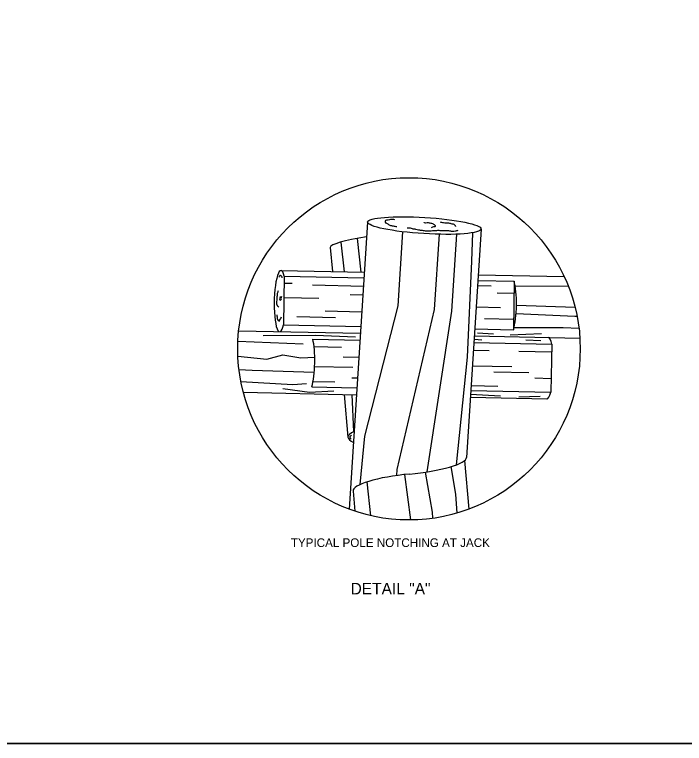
# Model space of a CAD drawing. Extents: x 49991.4 to 50021, y 49987.6 to 50011.4.
# Drawn here: x 50004.07 to 50008.69, y 49987.8 to 49992.83 of the extents above; entities that cross this region are included whole.
import ezdxf

# ---------------------------------------------------------------- set-up
doc = ezdxf.new("R2010")
doc.units = 0
for name, color, linetype in [('Level 1', 7, 'Continuous'), ('Level 2', 7, 'Continuous'), ('Level 3', 7, 'Continuous')]:
    doc.layers.add(name, color=color, linetype=linetype)

msp = doc.modelspace()

# ---------------------------------------------------------------- linework, layer by layer
at = {"layer": 'Level 1'}
for p, q in [((50006.5042, 49991.3972), (50006.376, 49989.4157)), ((50007.2869, 49991.3492), (50007.1873, 49989.7729)), ((50006.2469, 49991.2221), (50006.2626, 49991.0556)), ((50005.9062, 49991.0632), (50006.481, 49991.0506)), ((50005.9295, 49991.0237), (50005.925, 49990.6879)), ((50005.9295, 49991.0237), (50006.4785, 49991.0117)), ((50007.267, 49991.0336), (50007.8605, 49991.0205)), ((50005.9287, 49990.9761), (50005.9838, 49990.9749)), ((50006.125, 49990.9635), (50006.475, 49990.9558)), ((50007.2622, 49990.9583), (50007.3565, 49990.9563)), ((50007.2645, 49990.9946), (50007.5141, 49990.989)), ((50007.5141, 49990.989), (50007.5094, 49990.6535)), ((50007.3976, 49990.9099), (50007.5131, 49990.9073)), ((50005.9274, 49990.8762), (50006.1668, 49990.8713)), ((50006.384, 49990.8964), (50006.4711, 49990.8946)), ((50007.2529, 49990.8112), (50007.42, 49990.8074)), ((50006.2114, 49990.7843), (50006.4637, 49990.7786)), ((50006.0157, 49990.7443), (50006.282, 49990.7385)), ((50007.311, 49990.7324), (50007.5105, 49990.7281)), ((50005.925, 49990.6879), (50006.4571, 49990.6763)), ((50007.2433, 49990.6593), (50007.5095, 49990.6535)), ((50005.6148, 49990.6476), (50006.4539, 49990.6294)), ((50007.2404, 49990.6121), (50007.9685, 49990.5964)), ((50007.2612, 49990.6328), (50007.3729, 49990.6249)), ((50007.4886, 49990.6195), (50007.704, 49990.6275)), ((50006.1257, 49990.5897), (50006.453, 49990.5826)), ((50007.2374, 49990.5654), (50007.775, 49990.5537)), ((50007.2932, 49990.581), (50007.2413, 49990.5876)), ((50007.7, 49990.577), (50007.5963, 49990.5823)), ((50007.775, 49990.5537), (50007.7679, 49990.2235)), ((50006.1345, 49990.5387), (50006.3236, 49990.5345)), ((50007.2342, 49990.5142), (50007.3417, 49990.5118)), ((50007.5481, 49990.5069), (50007.7738, 49990.5018)), ((50006.3357, 49990.4673), (50006.4435, 49990.4647)), ((50006.1387, 49990.4013), (50006.4027, 49990.3956)), ((50007.2273, 49990.4057), (50007.5001, 49990.3999)), ((50007.376, 49990.3644), (50007.616, 49990.3591)), ((50006.3956, 49990.3232), (50006.4342, 49990.3224)), ((50007.6572, 49990.321), (50007.7699, 49990.3185)), ((50006.1186, 49990.2592), (50006.4279, 49990.2525)), ((50006.1275, 49990.2968), (50006.2778, 49990.2934)), ((50007.2186, 49990.2681), (50007.4017, 49990.2641)), ((50005.6468, 49990.2227), (50006.4267, 49990.2058)), ((50006.3413, 49990.2075), (50006.3688, 49989.9117)), ((50006.3961, 49990.2065), (50006.4058, 49989.9503)), ((50007.215, 49990.2103), (50007.4201, 49990.1989)), ((50007.2166, 49990.2354), (50007.7679, 49990.2235)), ((50007.2136, 49990.1884), (50007.7425, 49990.1772)), ((50007.5464, 49990.191), (50007.694, 49990.1949)), ((50007.1721, 49989.7505), (50007.2032, 49989.4158)), ((50006.4035, 49989.5407), (50006.4165, 49989.4014))]:
    msp.add_line(p, q, dxfattribs=at)
msp.add_lwpolyline([(49999.3835, 49998.9992), (50016.7501, 49998.9992), (50016.7501, 49987.7988), (49999.3835, 49987.7988)], close=True, dxfattribs=at)
for points in [[(50006.4517, 49989.5854), (50006.4858, 49989.9202), (50006.715, 49990.8191), (50006.7477, 49991.3301)], [(50006.7067, 49989.6479), (50006.7083, 49989.6902), (50006.9661, 49990.793), (50006.9996, 49991.3128)], [(50006.9153, 49989.6732), (50007.0848, 49990.7813), (50007.1195, 49991.3137)], [(50007.1178, 49989.7222), (50007.1936, 49990.4653), (50007.2222, 49991.1271), (50007.2295, 49991.3238)], [(50006.3436, 49991.0536), (50006.3212, 49991.2596)], [(50006.4596, 49991.0511), (50006.4343, 49991.2844)], [(50007.5218, 49990.9568), (50007.8887, 49990.9549)], [(50007.5313, 49990.8227), (50007.9352, 49990.8101)], [(50007.5288, 49990.7664), (50007.9327, 49990.7488), (50007.949, 49990.7482)], [(50007.514, 49990.6695), (50007.8542, 49990.6702), (50007.9623, 49990.6638)], [(50005.7826, 49990.614), (50006.1435, 49990.617), (50006.4208, 49990.6041)], [(50005.6094, 49990.5758), (50006.0601, 49990.5575)], [(50005.6093, 49990.4707), (50005.8082, 49990.4499), (50005.9189, 49990.4804), (50006.0427, 49990.4606), (50006.1394, 49990.4638)], [(50005.6168, 49990.3796), (50005.7067, 49990.3757), (50006.1359, 49990.3609)], [(50005.6299, 49990.2967), (50005.9885, 49990.276), (50006.0826, 49990.2819)], [(50005.92, 49990.2483), (50006.1024, 49990.224), (50006.2703, 49990.2331)], [(50007.1219, 49989.3887), (50007.1121, 49989.5187), (50007.0808, 49989.7096)], [(50006.8015, 49989.341), (50006.7608, 49989.6545)], [(50006.9551, 49989.3526), (50006.9527, 49989.3938), (50006.9029, 49989.6712)], [(50006.5267, 49989.3706), (50006.5013, 49989.6043)]]:
    msp.add_lwpolyline(points, dxfattribs=at)
msp.add_circle((50006.7895, 49990.5223), 1.1813, dxfattribs=at)
msp.add_ellipse((50006.8956, 49991.3732), major_axis=(0.3914, -0.024), ratio=0.143064, dxfattribs=at)
for centre, major_axis, ratio, start_param, end_param in [((50006.637, 49991.2626), (-0.3901, -0.0405), 0.126327, 5.06467, 6.283302), ((50005.9016, 49990.8512), (0.0046, 0.212), 0.196346, 5.667839, 9.277217), ((50007.4817, 49990.8178), (0.0045, 0.2108), 0.235179, 3.823598, 5.664286), ((50005.9016, 49990.8512), (0.0046, 0.212), 0.196346, 3.289309, 3.837956), ((50007.7453, 49990.3889), (0.0046, 0.212), 0.196346, 5.605404, 6.28209), ((50006.0932, 49990.4251), (0.0045, 0.2121), 0.217807, 3.819255, 5.605352), ((50007.7453, 49990.3889), (0.0046, 0.212), 0.196346, 3.14159, 3.821196), ((50006.7591, 49989.949), (0.3903, 0.0374), 0.201542, 2.653998, 3.141021), ((50006.7591, 49989.8773), (0.3903, -0.0374), 0.201542, 3.179946, 3.600158), ((50006.7978, 49989.7381), (0.3895, 0.0373), 0.201992, 4.679863, 6.251309), ((50006.794, 49989.5786), (0.3903, 0.0374), 0.201542, 1.555621, 3.157543)]:
    msp.add_ellipse(centre, major_axis=major_axis, ratio=ratio, start_param=start_param, end_param=end_param, dxfattribs=at)
for points in [[(50006.706, 49991.3635), (50006.6828, 49991.3682), (50006.6587, 49991.3736), (50006.6407, 49991.3847), (50006.6278, 49991.3958), (50006.6301, 49991.4093), (50006.6469, 49991.4129), (50006.6652, 49991.4169), (50006.6898, 49991.4157)], [(50006.7767, 49991.3567), (50006.7986, 49991.3567), (50006.8107, 49991.3523), (50006.8356, 49991.3491), (50006.8558, 49991.3446), (50006.8797, 49991.3405), (50006.9071, 49991.336), (50006.922, 49991.336), (50006.9619, 49991.3387), (50006.9621, 49991.3387), (50006.9877, 49991.3405), (50007.0183, 49991.3387), (50007.063, 49991.3387), (50007.0879, 49991.3343), (50007.1096, 49991.336), (50007.1299, 49991.3416)], [(50006.944, 49991.3597), (50006.9672, 49991.367), (50006.9731, 49991.3682), (50006.9621, 49991.3801), (50006.9582, 49991.3827), (50006.9359, 49991.389), (50006.9142, 49991.3914), (50006.8962, 49991.3914), (50006.894, 49991.3935)], [(50007.0039, 49991.399), (50007.0138, 49991.3958), (50007.0279, 49991.3946), (50007.0461, 49991.3914), (50007.063, 49991.3911), (50007.0847, 49991.3861), (50007.094, 49991.3847), (50007.1038, 49991.3786), (50007.1075, 49991.3727), (50007.1096, 49991.3682), (50007.1096, 49991.367)], [(50005.9136, 49991.0129), (50005.9124, 49991.0224), (50005.9028, 49991.0286), (50005.8995, 49991.0274), (50005.8925, 49991.0163)], [(50005.8879, 49990.9223), (50005.8808, 49990.9037), (50005.8784, 49990.8738), (50005.8807, 49990.8224), (50005.8907, 49990.8131)], [(50005.9002, 49990.8844), (50005.9015, 49990.8593), (50005.9082, 49990.8623), (50005.9083, 49990.8718), (50005.9119, 49990.8869)], [(50005.8784, 49990.7568), (50005.8809, 49990.7315), (50005.8874, 49990.7188), (50005.8955, 49990.7143), (50005.8971, 49990.717), (50005.9108, 49990.7421)]]:
    msp.add_spline(points, degree=3, dxfattribs=at)
msp.add_open_spline([(50006.3912, 49989.8978), (50006.3745, 49989.9155), (50006.3931, 49989.9259)], degree=2, dxfattribs=at)
at = {"layer": 'Level 3'}
msp.add_line((49999.3835, 49987.7988), (50016.7501, 49987.7988), dxfattribs=at)

# ---------------------------------------------------------------- texts
at = {"layer": 'Level 2'}
for s, height, p in [('TYPICAL POLE NOTCHING AT JACK', 0.06, (50005.9745, 49989.1543)), ('DETAIL "A"', 0.08, (50006.3866, 49988.8271))]:
    msp.add_text(s, height=height, dxfattribs=at).set_placement(p)

doc.saveas('drawing.dxf')
